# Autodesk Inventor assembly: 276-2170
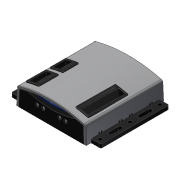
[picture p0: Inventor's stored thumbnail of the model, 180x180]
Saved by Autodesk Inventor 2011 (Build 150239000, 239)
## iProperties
Company: Autodesk Inc.
Created: 2010-06
Part Number: 276-2170
Document SubType Name: Assembly
Designer: Autodesk Inc.
Catalog Web Link: http://www.vexrobotics.com/products/accessories/logic/276-2170.html
Description: The VEX Microcontroller coordinates the flow of information and power on the robot.
Vendor: Innovation First, Inc.
Author: Autodesk Inc.
Title: VEX Robotics Kit of Parts
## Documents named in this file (8)
- D:\@VEX\BZ-Parts Kit\Logic\Microcontroller.iam
- D:\@VEX\BZ-Parts Kit\Logic\Microcontroller-Base.ipt
- D:\@VEX\BZ-Parts Kit\Logic\Microcontroller-Housing.ipt
- D:\@VEX\BZ-Parts Kit\Logic\MICROCONTROLLER-COVER-A.ipt
- D:\@VEX\BZ-Parts Kit\Logic\MICROCONTROLLER-COVER-B.ipt
- D:\@VEX\BZ-Parts Kit\Logic\MICROCONTROLLER-COVER-C.ipt
- D:\@VEX\BZ-Parts Kit\Logic\MICROCONTROLLER-PCB.iam
- D:\@VEX\BZ-Parts Kit\Logic\Microcontroller-Front.ipt
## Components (7 placed, 7 different names)
1. Microcontroller-Base:1 — Mate:1, Flush:1, Mate:2, Mate:12, Mate:13, Mate:14
2. Microcontroller-Housing:1 — Mate:1, Flush:1, Mate:2, Mate:3, Mate:4, Mate:5, Mate:6, Mate:7, Mate:8, Mate:9, Mate:10, Mate:11, Mate:15, Mate:16, Angle:1
3. MICROCONTROLLER-COVER-A:1 — Mate:3, Mate:4, Mate:5
4. MICROCONTROLLER-COVER-B:1 — Mate:9, Mate:10, Mate:11
5. MICROCONTROLLER-COVER-C:1 — Mate:6, Mate:7, Mate:8
6. MICROCONTROLLER-PCB:1 [sub-assembly] — Mate:12, Mate:13, Mate:14
7. Microcontroller-Front:1 — Mate:15, Mate:16, Angle:1
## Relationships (18: Mate 16, Flush 1, Angle 1)
- Mate:1: Microcontroller-Base:1 ↔ Microcontroller-Housing:1
- Flush:1: Microcontroller-Base:1 ↔ Microcontroller-Housing:1
- Mate:2: Microcontroller-Base:1 ↔ Microcontroller-Housing:1
- Mate:3: Microcontroller-Housing:1 ↔ MICROCONTROLLER-COVER-A:1
- Mate:4: Microcontroller-Housing:1 ↔ MICROCONTROLLER-COVER-A:1
- Mate:5: Microcontroller-Housing:1 ↔ MICROCONTROLLER-COVER-A:1
- Mate:6: Microcontroller-Housing:1 ↔ MICROCONTROLLER-COVER-C:1
- Mate:7: Microcontroller-Housing:1 ↔ MICROCONTROLLER-COVER-C:1
- Mate:8: Microcontroller-Housing:1 ↔ MICROCONTROLLER-COVER-C:1
- Mate:9: Microcontroller-Housing:1 ↔ MICROCONTROLLER-COVER-B:1
- Mate:10: Microcontroller-Housing:1 ↔ MICROCONTROLLER-COVER-B:1
- Mate:11: Microcontroller-Housing:1 ↔ MICROCONTROLLER-COVER-B:1
- Mate:12: Microcontroller-Base:1 ↔ MICROCONTROLLER-PCB:1
- Mate:13: Microcontroller-Base:1 ↔ MICROCONTROLLER-PCB:1
- Mate:14: Microcontroller-Base:1 ↔ MICROCONTROLLER-PCB:1
- Mate:15: Microcontroller-Housing:1 ↔ Microcontroller-Front:1
- Mate:16: Microcontroller-Housing:1 ↔ Microcontroller-Front:1
- Angle:1: Microcontroller-Housing:1 ↔ Microcontroller-Front:1
